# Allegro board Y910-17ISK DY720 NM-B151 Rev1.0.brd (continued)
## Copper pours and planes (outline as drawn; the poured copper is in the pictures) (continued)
GPU_SWN4 on BOTTOM (solid shape): 231.06,197.23 231.06,196.04 231.19,195.91 232,195.91 232.38,195.53 232.38,195.02 233.01,194.39 234.79,194.39 234.92,194.26 234.92,190.2 234.67,189.94 230.73,189.94 230.47,190.2 230.47,191.34 230.35,191.47 229.71,191.47 229.59,191.34 229.59,190.45 229.33,190.2 225.14,190.2 225.01,190.33 225.01,194.01 226.16,195.15 226.16,196.93 226.54,197.31 230.98,197.31
GPU_SWN5 on BOTTOM (solid shape): 218.87,197.23 218.87,196.04 218.99,195.91 220.06,195.91 220.31,195.66 220.31,195.41 220.44,195.28 220.82,195.28 222.47,193.63 222.47,191.21 221.46,190.2 218.41,190.2 218.16,190.45 218.16,191.34 218.03,191.47 217.52,191.47 217.39,191.34 217.39,190.07 217.14,189.82 214.47,189.82 213.58,190.71 213.58,197.06 213.84,197.31 218.79,197.31
GRM2103_OUT on TOP: 78.99,53.04 79.98,53.04 79.99,53.03 81.19,53.03 81.22,52.99 81.22,51.72 81.3,51.64 82.27,51.64 82.77,52.15 87.09,52.15 87.47,52.53 87.47,55.71 86.96,56.21 79.22,56.21 78.94,55.93 78.94,53.09
GRM2103_PVIN on TOP: 71.22,50.12 71.47,50.37 72.49,50.37 72.99,50.88 75.28,50.88 75.28,50.12 75.41,49.99 77.06,49.99 77.19,49.86 77.19,48.85 76.8,48.47 76.8,48.09 76.04,47.32 72.23,47.32 71.72,46.82 70.33,46.82 70.2,46.94 70.2,48.97 70.07,49.1 68.93,49.1 68.68,49.36 68.68,50.02 68.78,50.12
KBD_GND on TOP: 75.66,18.24 76.8,18.24 76.93,18.11 76.93,15.7 76.8,15.57 76.04,15.57 75.92,15.7 75.92,16.59 75.53,16.97 75.53,18.11
KBD_GND on IN05: 68.04,17.73 70.07,17.73 70.58,18.24 70.58,20.27 70.96,20.65 75.92,20.65 76.55,20.02 76.55,16.59 75.53,15.57 73.76,15.57 73.5,15.32 68.04,15.32 67.79,15.57 67.79,17.48
LAN_LX on TOP: 56.1,67.77 55.87,68 52.32,68 51.1,66.78 50.79,66.78 49.12,65.1 49.12,64.47 49.19,64.39 50.06,64.39 51.02,65.36 51.05,65.36 51.26,65.57 55.81,65.57 56.1,65.87
LG_3V on TOP (solid shape): 49.75,20.53 49.75,19.89 49.25,19.38 49.25,17.1 48.48,16.34 46.96,16.34 46.25,15.62 45.64,15.62 45.46,15.45 45.46,15.22 45.41,15.17 45.31,15.17 45.26,15.22 45.26,16.06 46.06,16.86 46.06,17.21 46.2,17.35 47.85,17.35 48.1,17.61 48.1,20.15 48.74,20.78 49.5,20.78
LG_5V on TOP: 43.86,15.98 43.86,15.24 43.78,15.17 43.66,15.17 43.58,15.24 43.58,15.32 43.07,15.83 42.67,15.83 42.06,16.44 42.06,16.69 42.21,16.84 42.67,16.84 43.35,16.16 43.68,16.16
LG_5V on TOP: 32.99,15.57 34.13,15.57 34.39,15.32 34.39,14.3 34.26,14.18 32.99,14.18 32.74,14.43 32.74,15.32
LG_5V on IN05: 32.86,15.57 34.01,15.57 34.13,15.45 34.13,14.56 33.88,14.3 32.86,14.3 32.74,14.43 32.74,15.45
LX_1.2V on BOTTOM: 113.63,81.23 113.76,81.11 117.95,81.11 118.59,81.74 118.59,87.46 118.21,87.84 115.67,87.84 115.29,87.46 115.29,84.66 115.16,84.66 114.9,84.41 113.89,84.41 113.63,84.15
MCT1_TL on TOP: 19.15,110.19 19.15,108.28 19.4,108.03 21.56,108.03 21.94,107.65 21.94,104.09 21.31,103.46 21.31,93.3 21.43,93.17 21.94,93.17 22.07,93.3 22.07,103.2 22.81,103.95 22.81,108.81 21.43,110.19
MIC1L_RING2 on BOTTOM: 297.61,26.65 300.78,26.65 300.83,26.6 300.83,25.68 300.78,25.63 299.84,25.63 299.74,25.73 297.53,25.73 297.48,25.78 297.48,26.52
MIC1R_SLEEVE on BOTTOM: 298.14,27.61 298.37,27.84 300.78,27.84 300.83,27.79 300.83,26.85 300.78,26.8 298.24,26.8 298.14,26.9
NVVDDS_B+ on TOP: 233.65,88.6 235.17,90.12 237.33,90.12 237.71,89.74 237.71,87.84 236.7,86.82 224.76,86.82 224.38,87.2 224.38,89.36 224.63,89.61 229.71,89.61 230.73,88.6
NVVDDS_B+ on BOTTOM: 222.22,90.5 222.22,87.07 222.47,86.82 226.66,86.82 227.17,86.31 229.97,86.31 230.09,86.19 230.09,85.17 230.22,85.04 233.52,85.04 234.79,86.31 237.71,86.31 238.09,86.69 238.09,89.49 238.48,89.87 238.48,90.38 238.35,90.5 234.28,90.5 234.16,90.38 234.16,89.36 233.78,88.98 231.87,88.98 231.81,89.04 230.28,89.04 228.7,90.63 222.35,90.63
NVVDDS_PH1 on BOTTOM: 232.89,95.2 233.01,95.08 238.09,95.08 238.22,95.2 238.22,96.47 238.86,97.11 238.86,99.01 238.48,99.39 233.14,99.39 232.89,99.14
NVVDDS_PH2 on BOTTOM: 220.9,94.97 224.15,94.97 224.84,94.29 225.65,94.29 225.75,94.39 225.75,95.81 225.78,95.84 225.78,98.94 225.39,99.32 220.95,99.32 220.77,99.14 220.77,95.1
NVVDDS_SN1 on BOTTOM: 238.98,96.6 239.75,96.6 239.87,96.47 239.87,94.31 239.75,94.19 238.98,94.19 238.86,94.31 238.86,96.47
NVVDDS_SN2 on BOTTOM: 226.54,95.66 226.54,94.06 226.66,93.93 226.66,93.3 226.69,93.27 227.35,93.27 227.43,93.35 227.43,95.66 227.38,95.71 226.59,95.71
SPKR_LED_GND on TOP: 304.39,101.04 305.53,101.04 305.91,101.43 306.8,101.43 306.93,101.3 306.93,99.65 306.67,99.39 304.39,99.39 304.26,99.52 304.26,100.92
SW1_5V on TOP (solid shape): 38.32,15.07 38.32,13.99 39.66,12.65 39.66,8.02 39.21,7.57 35.53,7.57 34.89,6.94 34.89,5.67 34.64,5.41 34.13,5.41 33.88,5.67 33.88,7.06 34.13,7.32 34.13,13.03 34.89,13.8 34.89,15.19 35.02,15.32 38.07,15.32
SW2_3V on TOP (solid shape): 54.58,20.53 54.58,13.64 53.49,12.55 53.49,11.2 52.92,10.63 52.19,10.63 52.18,10.62 50.85,10.62 50.54,10.32 50.29,10.32 50.1,10.51 50.1,14.21 50.13,14.25 50.13,20.65 50.26,20.78 54.33,20.78
TBT_SVR_IND on BOTTOM (solid shape): 47.21,98.12 47.21,93.42 46.83,93.04 46.83,92.41 46.92,92.32 46.92,92.3 46.89,92.06 47.03,91.86 47.03,91.57 47.13,91.48 47.13,91.37 47.29,91.21 47.29,91.03 47.24,90.98 47.14,90.98 46.89,90.73 46.89,90.63 46.8,90.55 46.71,90.55 46.64,90.61 46.64,91.15 46.27,91.52 46.2,91.52 46.09,91.63 46.02,91.73 45.93,91.79 44.67,93.04 44.67,98.12 44.8,98.25 47.09,98.25
TBTA_VBUS on TOP: 6.52,80.72 6.52,80.34 6.78,80.09 7.11,80.09 7.44,80.42 8.38,80.42 8.43,80.47 8.43,80.72 7.54,80.72 7.28,80.98 6.78,80.98
TBTA_VBUS on TOP: 8.43,77.93 8.43,78.21 8.38,78.26 7.44,78.26 7.18,78.51 6.62,78.51 6.5,78.39 6.5,77.91 6.65,77.75 7.16,77.75 7.34,77.93
TBTA_VBUS on BOTTOM: 31.64,77.3 31.85,77.3 32.1,77.04 32.1,76.79 32.35,76.79 32.86,77.3 32.86,79.78 32.67,79.98 32.67,80.46 32.3,80.83 31.39,80.83 31.21,81 28.39,81 28.04,80.65 28.04,77.8 28.34,77.5 29.71,77.5 29.89,77.68 31.26,77.68
TBTA_VBUS on BOTTOM: 12.42,80.98 17.62,80.98 17.88,80.72 17.88,77.68 17.5,77.3 12.29,77.3 12.03,77.55 12.03,80.6
TBTA_VBUS on IN05: 18.13,80.85 18.51,80.47 18.51,77.55 17.75,76.79 10.64,76.79 10.26,77.17 6.7,77.17 6.45,77.42 6.45,80.72 6.57,80.85
TBTA_VBUS on IN10: 18.77,77.55 16.73,75.52 9.49,75.52 8.48,76.53 6.95,76.53 6.45,77.04 6.45,80.98 6.57,81.11 7.34,81.11 7.84,81.61 10.05,81.61 10.47,82.03 16.64,82.03 18.51,83.9 26.39,83.9 26.63,83.66 29.05,83.66 30.7,82.01 30.7,78.36 29.56,77.22 26.94,77.22 26.61,77.55
TGR_1.2V on TOP: 112.87,88.01 112.44,88.45 112.44,88.65 112.24,88.85 111.48,88.85 111.45,88.83 111.45,88.5 111.73,88.22 111.73,87.07 111.6,86.95 111.6,86.19 111.73,86.06 112.24,86.06 112.49,86.31 112.49,86.77 113.3,87.58 113.3,87.89 113.18,88.01
TGR_3V on TOP: 49.88,25.48 49.75,25.35 47.59,25.35 47.47,25.48 47.47,25.86 48.48,26.88 49.75,26.88 49.88,26.75
TGR_3V on IN03: 48.1,26.75 48.61,26.75 48.86,26.5 48.86,25.1 48.74,24.97 47.98,24.97 47.85,25.1 47.85,26.5
TGR_5V on TOP (solid shape): 34.51,21.67 34.51,20.02 34.39,19.89 33.75,19.89 33.37,20.27 33.37,21.42 33.88,21.92 34.26,21.92
TP_LED_GND on TOP: 283.94,24.72 287.37,24.72 287.88,24.21 289.91,24.21 290.16,23.96 290.16,22.69 290.04,22.56 289.53,22.56 289.53,23.07 289.4,23.19 288.01,23.19 287.88,23.07 286.74,23.07 286.1,22.43 284.07,22.43 283.81,22.69 283.81,24.59
UG_3V on TOP (solid shape): 47.31,15.98 47.31,15.55 47.34,15.52 47.34,15.45 46.63,14.74 45.69,14.74 45.61,14.81 45.61,14.91 45.66,14.96 46.35,14.96 46.45,15.07 46.45,15.57 46.96,16.08 47.21,16.08
UG_3V on TOP: 51.15,26.24 51.15,25.48 51.02,25.35 50.39,25.35 50.26,25.48 50.26,26.24 50.13,26.37 50.13,26.75 50.26,26.88 51.15,26.88 51.28,26.75 51.28,26.37
UG_3V on IN05: 50.13,26.88 51.15,26.88 51.28,26.75 51.28,25.35 51.15,25.23 50.13,25.23 50.01,25.35 50.01,26.75
UG_5V on TOP (solid shape): 36.04,21.92 36.04,20.91 35.78,20.65 35.78,20.02 35.66,19.89 35.02,19.89 34.89,20.02 34.89,21.67 35.28,22.05 35.91,22.05
UG_5V on TOP: 43.4,14.74 42.11,14.74 41.78,15.07 41.78,15.45 41.96,15.62 42.31,15.62 42.97,14.96 43.38,14.96 43.45,14.89 43.45,14.79
UG_5V on BOTTOM: 34.97,21.67 36.8,21.67 36.88,21.59 36.88,21.01 36.77,20.91 34.97,20.91 34.77,21.11 34.77,21.47
V_PATH on TOP: 35.78,25.99 39.09,25.99 39.21,26.11 39.21,27.38 39.59,27.77 39.59,29.04 39.72,29.16 40.74,29.16 41.37,29.8 41.37,36.15 40.99,36.53 38.07,36.53 37.82,36.78 37.82,37.29 37.69,37.42 37.05,37.42 36.93,37.29 36.93,36.78 36.67,36.53 35.4,36.53 35.02,36.15 35.02,26.75
N16827117 on TOP: 30.07,103.08 31.08,103.08 31.21,102.95 31.21,92.66 30.96,92.41 30.32,92.41 29.94,92.79 29.94,102.95
N16827394 on TOP: 18.89,107.14 18.89,105.36 21.31,105.36 21.31,107.14
N17011706 on TOP: 269.26,37.32 267.76,37.32 267.74,37.34 267.74,37.72 268.29,38.28 268.29,38.94 268.42,39.07 269.62,39.07 269.69,38.99 269.69,37.75
N17011853 on TOP: 275.53,37.32 277.69,37.32 278,37.01 278.48,37.01 278.56,37.09 278.56,37.65 278.33,37.87 277.46,37.87 277.31,38.03 277.31,38.69 277.24,38.76 276.91,38.76 276.83,38.69 276.83,38 276.7,37.87 275.51,37.87 275.46,37.82 275.46,37.39
N17738807 on TOP: 276.96,46.43 276.96,44.91 278.35,44.91 278.35,46.43
N17791539 on TOP: 276.32,44.91 275.05,44.91 274.92,45.04 274.92,46.31 275.05,46.43 276.32,46.43 276.45,46.31 276.45,45.04
N18288666 on TOP: 110.08,21.67 110.97,20.78 110.97,14.3 110.46,13.8 101.57,13.8 100.81,14.56 100.81,18.37 101.19,18.75 102.2,18.75 102.46,19 102.46,19.26 102.84,19.64 103.47,19.64 104.11,20.27 104.11,21.42 104.36,21.67
N18346922 on BOTTOM (solid shape): 249.78,197.18 249.78,194.9 249.65,194.77 249.02,194.77 248.89,194.9 248.89,197.18 249.02,197.31 249.65,197.31
N18349859 on BOTTOM (solid shape): 213.08,197.31 213.08,195.28 212.95,195.15 212.31,195.15 212.19,195.28 212.19,197.31 212.31,197.44 212.95,197.44
N18350280 on BOTTOM (solid shape): 225.39,197.06 225.39,195.02 225.27,194.9 224.63,194.9 224.51,195.02 224.51,197.06 224.63,197.18 225.27,197.18
N18842312 on TOP (solid shape): 32.86,25.23 32.86,23.96 32.74,23.83 30.32,23.83 30.07,24.08 30.07,25.23 30.2,25.35 32.74,25.35
N20073337 on BOTTOM: 255.57,197.23 255.57,196.22 255.67,196.12 256.97,196.12 257.07,196.22 257.07,197.29 256.97,197.39 255.72,197.39
N20074453 on BOTTOM: 267.76,197.23 267.76,196.22 267.86,196.12 269.16,196.12 269.26,196.22 269.26,197.29 269.16,197.39 267.91,197.39
N20076374 on BOTTOM: 218.99,197.23 218.99,196.22 219.09,196.12 220.39,196.12 220.49,196.22 220.49,197.29 220.39,197.39 219.15,197.39
N20077877 on BOTTOM: 231.19,197.23 231.19,196.22 231.29,196.12 232.58,196.12 232.68,196.22 232.68,197.29 232.58,197.39 231.34,197.39
N20138043 on TOP: 113,86.95 114.52,86.95 114.78,86.69 114.78,86.06 114.65,85.93 113,85.93 112.87,86.06 112.87,86.82
N20153824 on TOP (solid shape): 269.08,64.72 269.08,58.35 269.96,57.47 269.96,53.46 270.35,53.06 270.35,49.86 270.1,49.61 268.07,49.61 267.94,49.74 267.94,53.04 267.43,53.55 267.43,63.94 268.4,64.9 268.9,64.9
N20154004 on TOP: 271.57,61.5 271.11,61.04 271.11,59.19 270.99,59.06 270.99,54.87 271.55,54.31 274.16,54.31 274.37,54.11 276.24,54.11 276.58,54.44 276.58,56.72 276.32,56.98 273.02,56.98 272.64,57.36 272.64,59.13 272.38,59.39 272.38,61.5
N20172556 on BOTTOM: 173.48,185.55 173.58,185.65 174.87,185.65 174.98,185.55 174.98,184.36 174.47,183.85 173.71,183.85 173.48,184.08
N20172566 on BOTTOM: 169.9,185.63 169.92,185.65 173.27,185.65 173.35,185.58 173.35,180.7 172.44,179.78 171.04,179.78 170.91,179.66 166.09,179.66 165.7,180.04 165.7,183.47 165.96,183.72 166.72,183.72 166.97,183.98 166.97,184.86 167.74,185.63
N20172725 on BOTTOM: 158.78,185.18 159.25,185.65 162.48,185.65 162.55,185.58 162.55,184.23 161.89,183.57 161.89,180.93 160.75,179.78 152.88,179.78 152.12,180.55 152.12,183.21 152.5,183.59 154.66,183.59 156.24,185.18
N20172772 on BOTTOM: 162.68,185.55 162.78,185.65 164.05,185.65 164.18,185.53 164.18,184.1 164.05,183.98 163.04,183.98 162.68,184.33
N20172887 on BOTTOM: 151.73,185.37 152.12,185.75 155.42,185.75 155.54,185.63 155.54,185.12 154.53,184.1 151.99,184.1 151.73,184.36
N21283256 on BOTTOM: 255.06,64.72 255.06,64.37 254.2,63.5 254.2,61.07 254.05,60.91 253.38,60.91 253.31,60.99 253.31,63.78 253.38,63.86 253.51,63.86 253.79,64.14 253.79,64.82 253.89,64.93 254.86,64.93
N21283256 on IN08: 242.46,59.24 242.46,58.19 242.72,57.94 247.11,57.94 249.6,60.43 252.78,60.43 253.82,61.47 253.82,62.36 253.74,62.44 253.08,62.44 252.5,61.85 248.86,61.85 246.81,59.8 243.02,59.8
N21871531 on TOP: 78.58,21.92 78.58,21.16 78.2,20.78 78.2,20.27 78.33,20.15 78.96,20.15 79.09,20.27 79.85,20.27 79.98,20.4 79.98,21.8 79.85,21.92
N22751755 on BOTTOM: 182.34,196.17 184.37,196.17 184.5,196.04 184.5,194.49 184.35,194.34 182.42,194.34 182.34,194.42
N22806527 on TOP (solid shape): 29.69,26.5 29.69,20.78 29.43,20.53 23.08,20.53 22.58,21.03 22.58,26.88 22.96,27.26 28.93,27.26
N22807451 on BOTTOM: 84.3,21.8 92.81,21.8 93.31,21.29 93.31,17.48 93.06,17.22 84.55,17.22 84.04,17.73 84.04,21.54
N23081959 on BOTTOM: 189.83,179.78 188.95,180.67 188.95,181.31 189.33,181.69 189.33,183.34 189.58,183.59 190.85,183.59 191.1,183.85 191.1,185.25 191.51,185.65 194.84,185.65 194.94,185.55 194.94,184.84 196.44,183.34 196.44,180.17 196.06,179.78
N23081993 on BOTTOM: 196.06,183.98 195.07,184.97 195.07,185.55 195.17,185.65 196.44,185.65 196.54,185.55 196.54,184.08 196.44,183.98
N23083331 on BOTTOM: 178.91,183.59 179.17,183.85 179.17,184.1 180.72,185.65 184.04,185.65 184.14,185.55 184.14,184.84 185.64,183.34 185.64,180.17 185.26,179.78 177.77,179.78 176.88,180.67 176.88,181.31 177.13,181.56 177.13,182.96 177.77,183.59
N23083370 on BOTTOM: 185.26,183.98 184.27,184.97 184.27,185.58 184.35,185.65 185.64,185.65 185.74,185.55 185.74,184.08 185.64,183.98
N23089660 on BOTTOM: 201.9,185.88 201.9,184.36 201.77,184.23 200.5,184.23 200.38,184.36 200.38,185.12 200.74,185.49 200.74,185.88 200.78,185.92 201.86,185.92
N23089662 on BOTTOM: 205.84,185.5 205.84,184.86 207.36,183.34 207.36,180.17 206.98,179.78 200.76,179.78 199.84,180.7 199.84,181.74 200.25,182.15 200.25,183.47 200.38,183.59 201.9,183.59 202.15,183.85 202.15,185.37 202.41,185.63 205.71,185.63
N23089706 on BOTTOM: 205.96,185.63 205.96,184.99 206.98,183.98 207.36,183.98 207.49,184.1 207.49,185.63 207.36,185.75 206.09,185.75
N23165924 on TOP: 165.58,186.64 165.58,185.88 164.56,184.86 164.31,184.86 164.05,184.61 164.05,183.85 164.18,183.72 164.94,183.72 166.34,185.12 166.34,186.52 166.21,186.64
N23166841 on TOP: 176.48,186.71 176.48,186.14 175.97,185.63 175.97,185.39 175.99,185.37 175.99,184.87 176.37,184.48 177.38,184.48 177.66,184.76 177.66,185.34 177.19,185.8 177.19,186.66 177.1,186.75 176.53,186.75
N25389389 on TOP (solid shape): 48.1,34.62 48.1,30.43 46.58,28.91 46.58,28.53 42.01,28.53 41.88,28.65 41.88,34.75 42.07,34.94 47.78,34.94
N25407327 on BOTTOM (solid shape): 261.84,197.06 261.84,195.02 261.72,194.9 261.08,194.9 260.95,195.02 260.95,197.06 261.08,197.18 261.72,197.18
N25470408 on BOTTOM: 152.59,200.87 153.5,200.87 153.65,200.72 153.65,199.4 153.37,199.12 152.66,199.12 152.56,199.02 152.28,199.02 152.16,199.15 152.16,199.96 152.18,199.99 152.18,200.47
N25470408 on BOTTOM: 152.24,200.87 153.51,200.87 153.77,200.61 153.77,199.34 153.64,199.22 153.13,199.22 152.75,199.6 152.75,199.72 152.5,199.98 152.24,199.98 152.12,200.1 152.12,200.74
N33525205 on BOTTOM (solid shape): 212.31,161.5 212.31,160.23 212.06,159.97 210.03,159.97 209.77,160.23 209.77,161.12 210.28,161.62 212.19,161.62
N33598415 on BOTTOM: 243.38,197.23 243.38,196.22 243.48,196.12 244.77,196.12 244.88,196.22 244.88,197.29 244.77,197.39 243.53,197.39
N33598972 on BOTTOM (solid shape): 237.46,196.93 237.46,194.9 237.33,194.77 236.7,194.77 236.57,194.9 236.57,196.93 236.7,197.06 237.33,197.06
N35284576 on BOTTOM: 208.76,123.02 208.76,124.54 209.14,124.92 211.3,124.92 211.42,124.79 211.42,123.02 211.3,122.89 208.88,122.89
N35284626 on TOP: 276.83,76.28 276.83,77.42 276.58,77.68 273.65,77.68 273.53,77.55 273.53,76.28 273.65,76.15 274.8,76.15 274.92,76.28 276.19,76.28 276.32,76.15 276.7,76.15
N36026261 on TOP (solid shape): 45.64,10.6 45.64,10.01 45.56,9.93 43.5,9.93 43.45,9.99 43.45,10.65 44.44,11.64 44.6,11.64
N36026271 on TOP (solid shape): 45.82,20.02 45.82,16.84 45.05,16.08 45.05,15.19 44.8,15.19 44.8,16.84 45.18,17.22 45.18,19.76 44.93,20.02 44.29,20.02 44.04,20.27 44.04,20.78 44.17,20.91 44.93,20.91
N36217862 on TOP: 211.17,124.03 211.93,124.03 212.06,123.9 217.9,123.9 218.41,123.4 218.41,121.75 218.28,121.62 217.52,121.62 217.39,121.75 211.3,121.75 211.04,122 211.04,123.9
N39195476 on TOP: 211.93,157.05 211.93,160.73 212.57,161.37 217.39,161.37 217.65,161.12 217.65,158.58 218.28,157.94 218.66,157.94 218.79,157.81 218.79,156.92 218.66,156.8 212.19,156.8
N39291118 on TOP: 290.29,170.26 297.66,170.26 297.78,170.13 297.78,166.58 297.4,166.2 290.16,166.2 289.91,166.45 289.91,169.88

Small or netless copper shapes (teardrops, artwork), in the pictures only: 53 on TOP, 8 on BOTTOM

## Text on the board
Ref Des/Silkscreen Bottom: Pb | e1 | REV:1.0 | Gaming Y | HF | 2016/08/17 | DY720 NM-B151 | +5V | GND | TXD | RXD | +3V | RTCRST_N
User.Comments: TOP | BOT
USER_PART_NUM_TOP: 203,5 | 312 | 1,5
User.18: TOP
User.19: BOT
User.40: Width/space | 6.7mil | 4.5 / 4.4 | L5/L7 | L1-TOP | L2-GND1 | L3-IN1 | L4-VCC | L5-IN2 | L6-IN3 | L7-GND2 | L8-BOT | LAYER | NAME | 88 ohm | Ref
User.41: FIGURE | SIZE | 8.0 | 10.0 | 16.0 | 28.0 | 36.0 | 98.0 | 118.0 | 126.0 | 166.0 | 26.0 | 43.0 | 55.0 | 63.0 | 49.0x26.0 | 55.0x20.0 | 56.0x32.0 | 63.0x20.0 | 65.0x16.0 | 67.0x24.0 | 67.0x35.0 | 74.0x32.0 | 83.0x35.0 | 87.0x24.0 | 91.0x28.0 | 104.0x28.0 | 110.0x35.0 | 197.0x118.0 | 37.0x26.0 | DRILL CHART: TOP to BOTTOM | ALL UNITS ARE IN MILS | TOLERANCE | +3.0/-3.0 | +2.0/-2.0 | PLATED | NON-PLATED | QTY | 87 | 345 | 3389 | 504 | 6830 | 9 | 12 | 8 | 15 | 4 | 3 | 6 | 1 | 7 | 2
